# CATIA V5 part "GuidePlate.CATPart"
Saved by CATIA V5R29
Part number: GuidePlate
Bounding box of the stored display mesh (mm): x -20 to 130, y -250 to 250, z 0 to 250
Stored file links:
  C:\Users\Administrator\Desktop\프로젝트\Boxfold\GuidePlate.CATPart
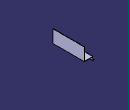
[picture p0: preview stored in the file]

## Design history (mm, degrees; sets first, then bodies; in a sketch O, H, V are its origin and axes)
Body1 (main body)
  DatumCurve1 to DatumCurve3
  Sketch1 on zx-plane, origin (0, 0, 0), H (1, 0, 0), V (0, 0, 1)
    point P1 (-20, 0)
    line L1 (-20, 0) -> (0, 0)
    line L2 (0, 0) -> (0, 50)
    line L3 (0, 50) -> (130, 50)
    line L4 (130, 50) -> (130, 250)
    point P4 (130, 250)
    reference projected line E1 (-20, -711) -> (-20, 0) from edge of DatumCurve3
    distance L4 L2 = 130
    distance L3 H = 50
    distance P4 L3 = 200
    coincidence: P1 H, P1 E1
    horizontal: L1 H, L3 H
    vertical: L2 V, L4 V
  Pad1: profile Sketch1, direction (0, -1, 0), length 250, mirrored extent, thin wall 5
